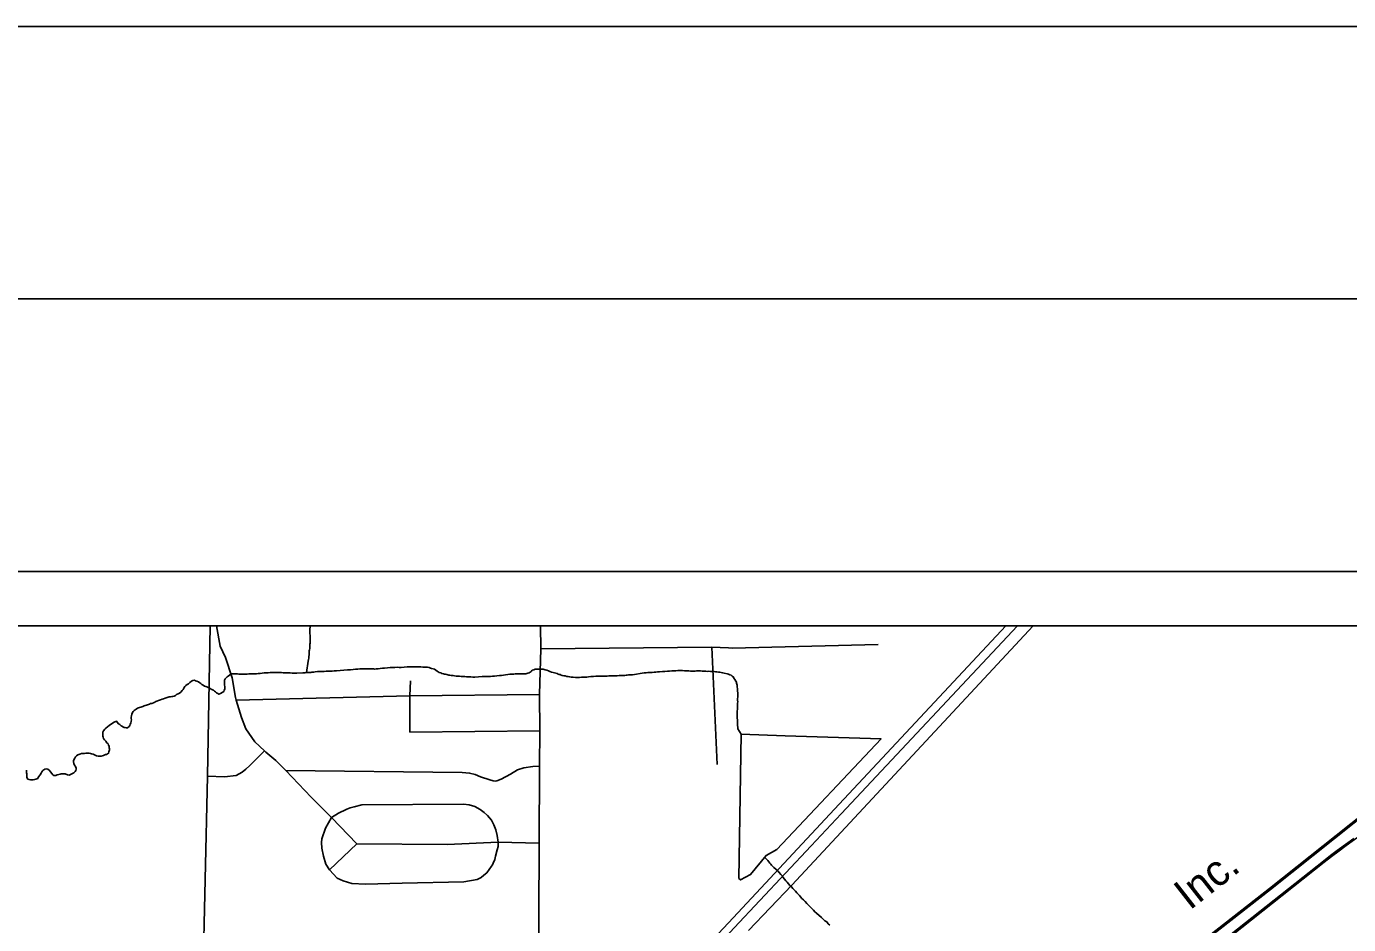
# Model space of a CAD drawing. Extents: x 0 to 44.3, y 0 to 22.
# Drawn here: x 5.6 to 8.026, y 20.352 to 22 of the extents above; entities that cross this region are included whole.
import ezdxf

# ---------------------------------------------------------------- set-up
doc = ezdxf.new("R2010")
doc.units = 0
for name, color, linetype in [('GM_X_City_Street', 7, 'Continuous'), ('GM_X_Corporation', 7, 'Continuous'), ('GM_X_County_Road', 7, 'Continuous'), ('GM_X_Minor_Lake', 7, 'Continuous'), ('GM_X_Minor_River', 7, 'Continuous'), ('GM_X_Rail_Line', 7, 'Continuous'), ('GM_X_Rail_Line_Text', 7, 'Continuous'), ('GM_X_State_Route', 7, 'Continuous'), ('SH_Border', 7, 'Continuous'), ('SH_Cut_Line', 7, 'Continuous'), ('SH_Data', 7, 'Continuous')]:
    doc.layers.add(name, color=color, linetype=linetype)

msp = doc.modelspace()

# ---------------------------------------------------------------- linework, layer by layer
at = {"layer": 'GM_X_City_Street'}
for p, q in [((6.8677, 20.6458), (6.858, 20.8609)), ((6.3041, 20.7719), (6.3048, 20.799)), ((6.3041, 20.7049), (6.3041, 20.7719)), ((6.3041, 20.7049), (6.5422, 20.7076)), ((6.1565, 20.4521), (6.2068, 20.5))]:
    msp.add_line(p, q, dxfattribs=at)
for points in [[(5.9492, 20.9), (5.9557, 20.863), (5.9657, 20.8418), (5.9777, 20.8046), (5.9837, 20.7687), (5.9853, 20.7635), (5.9948, 20.7321), (6.0032, 20.7113), (6.0193, 20.6871), (6.0374, 20.6705), (6.0395, 20.6686), (6.0578, 20.6531), (6.0763, 20.6345), (6.1231, 20.5858), (6.1599, 20.5486), (6.2068, 20.5), (6.3721, 20.4986), (6.4661, 20.5031), (6.5411, 20.5015)], [(6.8885, 20.8595), (6.8956, 20.8591), (7.1632, 20.8658)], [(6.544, 20.858), (6.858, 20.8609), (6.8885, 20.8595)], [(5.9853, 20.7635), (6.3041, 20.7719), (6.542, 20.7739)], [(5.9326, 20.6242), (5.9635, 20.6233), (5.9855, 20.6257), (5.9965, 20.6317), (6.0031, 20.6369), (6.0104, 20.6437), (6.0374, 20.6705)], [(6.0763, 20.6345), (6.3999, 20.6308), (6.4134, 20.6299), (6.4239, 20.6272), (6.4333, 20.6233), (6.4504, 20.6177), (6.4569, 20.6159), (6.4603, 20.6154), (6.4636, 20.6159), (6.4715, 20.6189), (6.4887, 20.6279), (6.5017, 20.6359), (6.5133, 20.6395), (6.5294, 20.6418), (6.5417, 20.6424)], [(6.1599, 20.5486), (6.1729, 20.5565), (6.1779, 20.5586), (6.1821, 20.5605), (6.188, 20.5636), (6.1942, 20.5663), (6.202, 20.5683), (6.2155, 20.5714), (6.4025, 20.5727)], [(6.4031, 20.4302), (6.4275, 20.4345), (6.431, 20.4365), (6.4345, 20.4386), (6.4399, 20.4424), (6.4454, 20.447), (6.4539, 20.4589), (6.4555, 20.4615), (6.4569, 20.4646), (6.4598, 20.4712), (6.4612, 20.4776), (6.4639, 20.4893), (6.4657, 20.4955), (6.4661, 20.5031), (6.4643, 20.5156), (6.4617, 20.526), (6.4583, 20.5351), (6.4536, 20.5434), (6.4463, 20.5518), (6.4401, 20.5578), (6.4327, 20.5634), (6.4229, 20.5685), (6.4127, 20.5714), (6.4025, 20.5727)], [(6.1565, 20.4521), (6.1496, 20.4625), (6.1453, 20.4773), (6.1424, 20.4924), (6.142, 20.5028), (6.1424, 20.5094), (6.1491, 20.5288), (6.1599, 20.5486)], [(6.1565, 20.4521), (6.1706, 20.4372), (6.1816, 20.432), (6.1976, 20.4271), (6.2223, 20.4261), (6.2898, 20.428), (6.4031, 20.4302)]]:
    msp.add_lwpolyline(points, dxfattribs=at)
at = {"layer": 'GM_X_Corporation'}
for points in [[(8.9, 14.1), (8.9, 20.9), (3.6041, 20.9)], [(8.9, 14.1), (8.9, 20.9), (3.6041, 20.9)], [(6.3816, 18.3424), (6.3804, 18.468), (6.2537, 18.4805), (6.0759, 18.768), (6.0133, 18.7265), (6.0126, 18.7328), (5.9906, 18.939), (5.8933, 18.8882), (5.9054, 19.4386), (5.9198, 20.0555), (5.9324, 20.6242), (5.9378, 20.9), (4.9066, 20.9)], [(8.2369, 18.3305), (8.2337, 18.6163), (8.648, 18.6417), (8.6432, 18.7252), (8.6245, 18.7283), (8.6223, 18.8598), (8.8575, 18.8766), (8.845, 19.3119), (8.9, 19.3141), (8.9, 20.9), (5.9378, 20.9), (5.9324, 20.6242), (5.9198, 20.0555), (5.9054, 19.4386), (5.8933, 18.8882), (5.9906, 18.939), (6.0126, 18.7328), (6.0133, 18.7265), (6.0759, 18.768), (6.2537, 18.4805), (6.3804, 18.468), (6.3816, 18.3424)]]:
    msp.add_lwpolyline(points, dxfattribs=at)
at = {"layer": 'GM_X_County_Road'}
msp.add_lwpolyline([(6.9254, 20.341), (7.0049, 20.4244), (7.4479, 20.9)], dxfattribs=at)
at = {"layer": 'GM_X_Minor_Lake'}
for points in [[(6.9116, 20.7012), (6.9077, 20.4368), (6.9108, 20.4338), (6.9292, 20.4438), (6.9577, 20.4788), (6.9776, 20.49), (7.1686, 20.6926), (6.9926, 20.6985)], [(6.9926, 20.6985), (6.9116, 20.7012)]]:
    msp.add_lwpolyline(points, dxfattribs=at)
at = {"layer": 'GM_X_Minor_River'}
for points in [[(6.1145, 20.8144), (6.1173, 20.8353), (6.118, 20.8384), (6.1184, 20.8407), (6.1187, 20.8437), (6.1191, 20.8472), (6.1191, 20.8494), (6.119, 20.8517), (6.1194, 20.854), (6.1197, 20.8563), (6.1201, 20.8586), (6.1201, 20.8609), (6.1204, 20.8628), (6.1204, 20.8662), (6.1207, 20.8685), (6.1207, 20.8719), (6.121, 20.8753), (6.121, 20.8784), (6.121, 20.8807), (6.121, 20.8826), (6.1205, 20.886), (6.1205, 20.8879), (6.1205, 20.8898), (6.1205, 20.8921), (6.1204, 20.8947), (6.1208, 20.8974), (6.1208, 20.8997), (6.1208, 20.9)], [(6.0807, 20.8137), (6.0842, 20.8137), (6.088, 20.8134), (6.0918, 20.8134), (6.0967, 20.8134), (6.1077, 20.8139), (6.1119, 20.814), (6.1164, 20.8148), (6.1194, 20.8148), (6.1221, 20.8148), (6.124, 20.8152), (6.1278, 20.8153), (6.1304, 20.8157), (6.1346, 20.8161), (6.138, 20.8161), (6.1407, 20.8162), (6.1437, 20.8166), (6.1464, 20.8166), (6.1502, 20.817), (6.1536, 20.8171), (6.1574, 20.8171), (6.1615, 20.8171), (6.1653, 20.8175), (6.1695, 20.8176), (6.1763, 20.818), (6.1828, 20.8189), (6.1892, 20.8193), (6.1949, 20.8197), (6.1999, 20.8202), (6.204, 20.8206), (6.2082, 20.8206), (6.212, 20.8211), (6.2158, 20.8211), (6.2192, 20.8215), (6.2219, 20.8215), (6.2245, 20.8212), (6.2275, 20.8212), (6.2298, 20.8212), (6.2325, 20.8213), (6.2348, 20.8213), (6.237, 20.8213), (6.2393, 20.8209), (6.2424, 20.8214), (6.2458, 20.8214), (6.2496, 20.8218), (6.2537, 20.8222), (6.2575, 20.8226), (6.2632, 20.8231), (6.2678, 20.8235), (6.2723, 20.8236), (6.2765, 20.8236), (6.2807, 20.824), (6.2845, 20.8237), (6.2879, 20.8237), (6.2989, 20.8246), (6.3027, 20.8246), (6.3065, 20.825), (6.3114, 20.8251), (6.3152, 20.8251), (6.3186, 20.8248), (6.3216, 20.8248), (6.3243, 20.8248), (6.3277, 20.8245), (6.3311, 20.8245), (6.3338, 20.8242), (6.3361, 20.8242), (6.3391, 20.8235), (6.3418, 20.8227), (6.3437, 20.822), (6.3467, 20.8212), (6.349, 20.8205), (6.3513, 20.819), (6.354, 20.8168), (6.3578, 20.8145), (6.3605, 20.8138), (6.3628, 20.8127), (6.3654, 20.8119), (6.3677, 20.8116), (6.3696, 20.8112), (6.3715, 20.8108), (6.3753, 20.8097), (6.3772, 20.8094), (6.3799, 20.809), (6.3833, 20.8087), (6.386, 20.8083), (6.389, 20.808), (6.3921, 20.808), (6.3951, 20.8076), (6.3978, 20.8073), (6.4008, 20.8069), (6.4046, 20.807), (6.408, 20.8066), (6.4122, 20.8067), (6.416, 20.8063), (6.4194, 20.806), (6.4232, 20.806), (6.4365, 20.8069), (6.441, 20.807), (6.4448, 20.807), (6.4482, 20.807), (6.4517, 20.8074)], [(6.4517, 20.8074), (6.4554, 20.8079), (6.4592, 20.8079), (6.4634, 20.8083), (6.4687, 20.8088), (6.4721, 20.8092), (6.4755, 20.8096), (6.4797, 20.8104), (6.4835, 20.8108), (6.4873, 20.8112), (6.4903, 20.8116), (6.4926, 20.8117), (6.4945, 20.8117), (6.4971, 20.8121), (6.5006, 20.8121), (6.5028, 20.8121), (6.5063, 20.8122), (6.5097, 20.8122), (6.5127, 20.8119), (6.515, 20.8119), (6.5169, 20.8119), (6.5207, 20.8135), (6.5229, 20.8139), (6.5267, 20.8166), (6.5286, 20.8185), (6.5312, 20.8193), (6.5339, 20.8208), (6.5418, 20.8209), (6.5449, 20.8209), (6.5483, 20.8206), (6.5502, 20.8202), (6.5521, 20.8195), (6.5551, 20.8188), (6.5582, 20.8176), (6.5609, 20.8165), (6.5639, 20.8154), (6.5666, 20.8147), (6.5692, 20.8139), (6.5719, 20.8132), (6.5742, 20.8125), (6.5761, 20.8117), (6.578, 20.811), (6.5799, 20.8106), (6.5818, 20.8099), (6.5837, 20.8091), (6.5864, 20.8084), (6.589, 20.8081), (6.5917, 20.8073), (6.5944, 20.807), (6.597, 20.8066), (6.6001, 20.8059), (6.6035, 20.8059), (6.6077, 20.8056), (6.6115, 20.8052), (6.6153, 20.8053), (6.6187, 20.8057), (6.6225, 20.8057), (6.6255, 20.8061), (6.6289, 20.8062), (6.632, 20.8066), (6.6361, 20.807), (6.6407, 20.807), (6.6452, 20.8075), (6.6498, 20.8079), (6.6536, 20.8079), (6.6562, 20.808), (6.6585, 20.8076), (6.6604, 20.8076), (6.6631, 20.8076), (6.6657, 20.8077), (6.6691, 20.8081), (6.6729, 20.8081), (6.6771, 20.8082), (6.6805, 20.8086), (6.6843, 20.8086), (6.6881, 20.8087), (6.6904, 20.8087), (6.6942, 20.8091), (6.6984, 20.8091), (6.7006, 20.8095), (6.7025, 20.8099), (6.7052, 20.8103), (6.7075, 20.8104), (6.7125, 20.8104)], [(6.7125, 20.8104), (6.7339, 20.8141), (6.7373, 20.8141), (6.7407, 20.8142), (6.7449, 20.8143), (6.7487, 20.8148), (6.7521, 20.8153), (6.7552, 20.8154), (6.7586, 20.8158), (6.762, 20.8159), (6.7673, 20.8161), (6.7719, 20.8166), (6.7765, 20.8167), (6.7806, 20.8172), (6.7844, 20.8176), (6.7883, 20.8177), (6.7921, 20.8178), (6.7959, 20.8183), (6.8, 20.8184), (6.8042, 20.8181), (6.8077, 20.8178), (6.8115, 20.8176), (6.8161, 20.8173), (6.8191, 20.817), (6.8226, 20.8171), (6.8252, 20.8172), (6.8275, 20.8172), (6.8298, 20.8173), (6.8325, 20.8173), (6.8347, 20.8174), (6.8374, 20.8175), (6.8401, 20.8171), (6.8431, 20.8172), (6.8469, 20.8169), (6.85, 20.8166), (6.8527, 20.8167), (6.8553, 20.8164), (6.8576, 20.8165), (6.8599, 20.8161), (6.8622, 20.8162), (6.8649, 20.8159), (6.8675, 20.8156), (6.8702, 20.8153), (6.8729, 20.8149), (6.8752, 20.8142), (6.8779, 20.8139), (6.8809, 20.8132), (6.8863, 20.8122), (6.8886, 20.8115), (6.8913, 20.8105), (6.8932, 20.8094), (6.8955, 20.8079), (6.8979, 20.806), (6.8987, 20.8042), (6.9003, 20.8019), (6.9023, 20.7989), (6.9031, 20.7967), (6.9035, 20.7948), (6.9044, 20.7914), (6.9048, 20.7895), (6.9048, 20.7876), (6.9053, 20.7849), (6.9053, 20.783), (6.9054, 20.7803), (6.9059, 20.7773), (6.9056, 20.7742), (6.9056, 20.772), (6.9057, 20.7693), (6.9054, 20.7666), (6.9054, 20.764), (6.9055, 20.7609), (6.9052, 20.7582), (6.9053, 20.7544), (6.905, 20.7521), (6.905, 20.7502), (6.9051, 20.7472), (6.9048, 20.7434), (6.9046, 20.7365), (6.905, 20.7224), (6.905, 20.7197), (6.9051, 20.7175), (6.9056, 20.7144), (6.906, 20.7114), (6.9116, 20.7012)], [(5.8358, 20.7602), (5.8376, 20.761), (5.8399, 20.7618), (5.8429, 20.7634), (5.8463, 20.7645), (5.8494, 20.7653), (5.852, 20.7661), (5.855, 20.7673), (5.8622, 20.7696), (5.8649, 20.77), (5.8671, 20.7704), (5.869, 20.7705), (5.8717, 20.7713), (5.8736, 20.772), (5.8755, 20.774), (5.8789, 20.7755), (5.8811, 20.7767), (5.8838, 20.7786), (5.8864, 20.7813), (5.8879, 20.7836), (5.889, 20.7859), (5.8912, 20.7886), (5.8931, 20.7905), (5.8954, 20.7924), (5.8976, 20.7936), (5.9003, 20.7959), (5.9033, 20.7986), (5.9055, 20.8001), (5.9086, 20.8002), (5.9108, 20.7994), (5.9128, 20.7987), (5.9158, 20.7972), (5.9185, 20.7953), (5.9204, 20.7942), (5.9223, 20.7927), (5.9246, 20.7912), (5.9273, 20.7897), (5.9296, 20.789), (5.9315, 20.7882), (5.9349, 20.7863), (5.9376, 20.7852), (5.9395, 20.7841), (5.9418, 20.783), (5.9437, 20.7819), (5.9456, 20.7804), (5.9475, 20.7789), (5.9494, 20.7773), (5.9513, 20.7762), (5.9536, 20.7747), (5.9563, 20.7759), (5.9597, 20.7778), (5.9623, 20.7794), (5.963, 20.7821), (5.9642, 20.784), (5.9645, 20.7866), (5.9645, 20.7889), (5.9641, 20.7912), (5.964, 20.7942), (5.9636, 20.7977), (5.964, 20.8003), (5.9651, 20.8026), (5.9666, 20.8045), (5.9685, 20.8065), (5.9703, 20.808), (5.973, 20.8099), (5.9752, 20.8115), (5.9775, 20.8119), (5.9802, 20.8123), (5.9821, 20.8123), (5.9851, 20.812), (5.9878, 20.812), (5.99, 20.8116), (5.9923, 20.8116), (5.995, 20.8117), (5.9976, 20.8113), (6.0014, 20.8114), (6.0052, 20.8114), (6.0086, 20.8118), (6.0109, 20.8118), (6.0128, 20.8118), (6.0155, 20.8123), (6.0193, 20.8123), (6.0223, 20.8123), (6.0257, 20.8127), (6.0291, 20.8128), (6.0329, 20.8132), (6.0363, 20.8136), (6.0401, 20.814), (6.0439, 20.8141), (6.0473, 20.8145), (6.0507, 20.8145), (6.0542, 20.8145), (6.0572, 20.8146), (6.0606, 20.8146), (6.0625, 20.8146), (6.0652, 20.8143), (6.0682, 20.8143), (6.0712, 20.8139), (6.0743, 20.814), (6.0773, 20.8136), (6.0807, 20.8137)], [(5.6695, 20.6288), (5.6714, 20.6285), (5.6756, 20.6266), (5.679, 20.6259), (5.6824, 20.6278), (5.685, 20.6294), (5.6873, 20.6305), (5.6899, 20.6328), (5.691, 20.6348), (5.6914, 20.637), (5.6914, 20.6389), (5.6906, 20.642), (5.6886, 20.6446), (5.6875, 20.6473), (5.6867, 20.6503), (5.687, 20.6522), (5.6874, 20.6541), (5.6889, 20.6572), (5.6904, 20.6595), (5.6922, 20.6614), (5.6945, 20.6633), (5.6983, 20.6649), (5.7017, 20.6657), (5.704, 20.6657), (5.707, 20.6661), (5.7096, 20.6665), (5.7119, 20.6665), (5.715, 20.6666), (5.718, 20.6658), (5.7199, 20.6655), (5.7226, 20.6644), (5.7253, 20.6632), (5.7287, 20.6618), (5.7317, 20.661), (5.7355, 20.6611), (5.7378, 20.6607), (5.7416, 20.6619), (5.7454, 20.6638), (5.7473, 20.6642), (5.7491, 20.6654), (5.751, 20.6662), (5.7518, 20.6688), (5.7521, 20.6707), (5.7525, 20.6727), (5.7525, 20.6746), (5.7524, 20.6765), (5.752, 20.6791), (5.7512, 20.6814), (5.7501, 20.6837), (5.7482, 20.6852), (5.7462, 20.6882), (5.7439, 20.6908), (5.742, 20.6935), (5.7412, 20.6958), (5.7408, 20.6977), (5.7404, 20.7007), (5.7404, 20.703), (5.7407, 20.7053), (5.7418, 20.7076), (5.7441, 20.7106), (5.7463, 20.7125), (5.7493, 20.7149), (5.7524, 20.7172), (5.7565, 20.7206), (5.7614, 20.7234), (5.7655, 20.7253), (5.7671, 20.7234), (5.7694, 20.7204), (5.7717, 20.7189), (5.7744, 20.7166), (5.7797, 20.7136), (5.7816, 20.7133), (5.7839, 20.7129), (5.7858, 20.7129), (5.7888, 20.7153), (5.7903, 20.7175), (5.791, 20.7195), (5.7922, 20.7214), (5.7925, 20.7252), (5.7929, 20.7275), (5.7928, 20.7301), (5.7928, 20.7324), (5.7931, 20.7351), (5.7935, 20.7381), (5.795, 20.7412), (5.7961, 20.7431), (5.798, 20.745), (5.7999, 20.7462), (5.8017, 20.7473), (5.804, 20.7489), (5.8078, 20.7501), (5.81, 20.7509), (5.8138, 20.752), (5.8161, 20.7532), (5.8184, 20.754), (5.8206, 20.7548), (5.8259, 20.7567), (5.8282, 20.7575), (5.8305, 20.7579), (5.8335, 20.7591), (5.8358, 20.7602)], [(5.6003, 20.635), (5.6007, 20.6327), (5.6007, 20.6304), (5.6008, 20.6285), (5.6008, 20.6266), (5.6008, 20.6236), (5.6012, 20.6217), (5.6028, 20.619), (5.6051, 20.6179), (5.6081, 20.6176), (5.6104, 20.6176), (5.6126, 20.6176), (5.6153, 20.618), (5.6179, 20.6188), (5.621, 20.62), (5.6228, 20.623), (5.6255, 20.6265), (5.6273, 20.6296), (5.6288, 20.6322), (5.6303, 20.6345), (5.6322, 20.6361), (5.6344, 20.6372), (5.6363, 20.6376), (5.6398, 20.6369), (5.6428, 20.6347), (5.6444, 20.6324), (5.6467, 20.629), (5.649, 20.6267), (5.6509, 20.6256), (5.6543, 20.6256), (5.657, 20.6268), (5.66, 20.6276), (5.6623, 20.628), (5.6642, 20.6284), (5.6672, 20.6288), (5.6695, 20.6288)], [(7.0745, 20.3508), (7.0717, 20.3534), (7.069, 20.3567), (7.0655, 20.3589), (7.0624, 20.3619), (7.0593, 20.3648), (7.0499, 20.373), (7.0472, 20.3756), (7.0444, 20.3786), (7.0417, 20.3812), (7.039, 20.3838), (7.0362, 20.3867), (7.0323, 20.3908), (7.0292, 20.3942), (7.026, 20.3975), (7.0233, 20.4001), (7.0206, 20.4027), (7.0186, 20.4053), (7.0163, 20.4079), (7.0139, 20.4105), (7.0115, 20.4131), (7.0092, 20.4158), (7.0069, 20.418), (7.0045, 20.4213), (7.001, 20.4239), (6.9986, 20.4265), (6.9963, 20.4295), (6.9939, 20.4321), (6.9916, 20.4351), (6.9892, 20.4381), (6.9868, 20.4411), (6.9845, 20.4441), (6.9817, 20.4474), (6.979, 20.4504), (6.9755, 20.4534), (6.972, 20.4567), (6.9696, 20.4593), (6.9677, 20.4612), (6.9661, 20.463), (6.9645, 20.4649), (6.9629, 20.4668), (6.9606, 20.4697), (6.9549, 20.4754)]]:
    msp.add_lwpolyline(points, dxfattribs=at)
at = {"layer": 'GM_X_Rail_Line'}
for points in [[(5.5651, 18.768), (5.6149, 18.7757), (5.6654, 18.7876), (5.729, 18.8053), (5.8051, 18.8321), (5.8822, 18.8667), (5.9499, 18.9049), (5.9965, 18.9325), (6.0494, 18.9705), (6.2783, 19.1515), (6.6511, 19.4487), (7.068, 19.777), (7.5069, 20.1249), (7.8816, 20.4181), (8.1527, 20.6341), (8.4876, 20.9)], [(5.5655, 18.7657), (5.6154, 18.7734), (5.666, 18.7854), (5.7297, 18.8031), (5.806, 18.8299), (5.8833, 18.8646), (5.9511, 18.9029), (6.0009, 18.9316), (6.0543, 18.9694), (6.2802, 19.1482), (6.6557, 19.4469), (7.0742, 19.7774), (7.5083, 20.1231), (7.883, 20.4163), (8.1542, 20.6323), (8.4913, 20.9)], [(7.7099, 20.2542), (7.7535, 20.2857), (7.9816, 20.4663), (7.9949, 20.4769), (8.0069, 20.4857), (8.022, 20.497), (8.0372, 20.5078), (8.0558, 20.5206), (8.082, 20.5381), (8.1087, 20.5557), (8.2183, 20.6282), (8.2248, 20.6325)], [(5.5884, 18.5876), (5.6031, 18.5945), (5.6177, 18.6024), (5.6308, 18.6101), (5.644, 18.6187), (5.6646, 18.633), (5.681, 18.6455), (6.0246, 18.9178), (6.1153, 18.9899), (6.2212, 19.0736), (6.3387, 19.1668), (6.4128, 19.2255), (6.507, 19.3002), (6.6206, 19.3902), (6.7271, 19.4749), (7.0841, 19.7577), (7.3744, 19.988), (7.7059, 20.251), (7.9801, 20.4681), (7.9935, 20.4787), (8.0055, 20.4876), (8.0206, 20.4989), (8.0359, 20.5097)]]:
    msp.add_lwpolyline(points, dxfattribs=at)
at = {"layer": 'GM_X_State_Route'}
for p, q in [((6.544, 20.858), (6.5435, 20.9)), ((7.0832, 20.5636), (7.3973, 20.9)), ((7.0956, 20.5552), (7.419, 20.9)), ((7.0403, 20.4962), (7.0956, 20.5552))]:
    msp.add_line(p, q, dxfattribs=at)
for points in [[(6.5408, 20.3664), (6.5411, 20.5015), (6.5417, 20.6424), (6.5422, 20.7076), (6.542, 20.7739), (6.544, 20.858)], [(6.757, 20.2152), (6.8884, 20.3551), (7.0832, 20.5636)], [(6.5325, 19.9546), (6.5345, 19.9568), (6.5782, 20.0026), (6.6682, 20.0979), (6.7685, 20.2042), (6.8992, 20.3458), (7.0403, 20.4962)], [(6.5368, 20.0965), (6.5376, 20.1477), (6.5402, 20.2384), (6.5406, 20.304), (6.5408, 20.3664)]]:
    msp.add_lwpolyline(points, dxfattribs=at)
at = {"layer": 'SH_Border'}
msp.add_lwpolyline([(1.5, 21.5), (33.5, 21.5), (33.5, 0.5), (1.5, 0.5)], close=True, dxfattribs=at)
at = {"layer": 'SH_Cut_Line'}
for points in [[(0, 0), (34, 0), (34, 22), (0, 22)], [(0, 22), (34, 22), (34, 0), (0, 0)]]:
    msp.add_lwpolyline(points, close=True, dxfattribs=at)
at = {"layer": 'SH_Data'}
for p, q in [((2, 21), (9, 21)), ((2.1, 20.9), (8.9, 20.9)), ((2.1, 20.9), (8.9, 20.9))]:
    msp.add_line(p, q, dxfattribs=at)

# ---------------------------------------------------------------- texts
at = {"layer": 'GM_X_Rail_Line_Text'}
msp.add_text('Inc.', height=0.05663, rotation=38.0239, dxfattribs=at).set_placement((7.7348, 20.3771))

doc.saveas('drawing.dxf')
